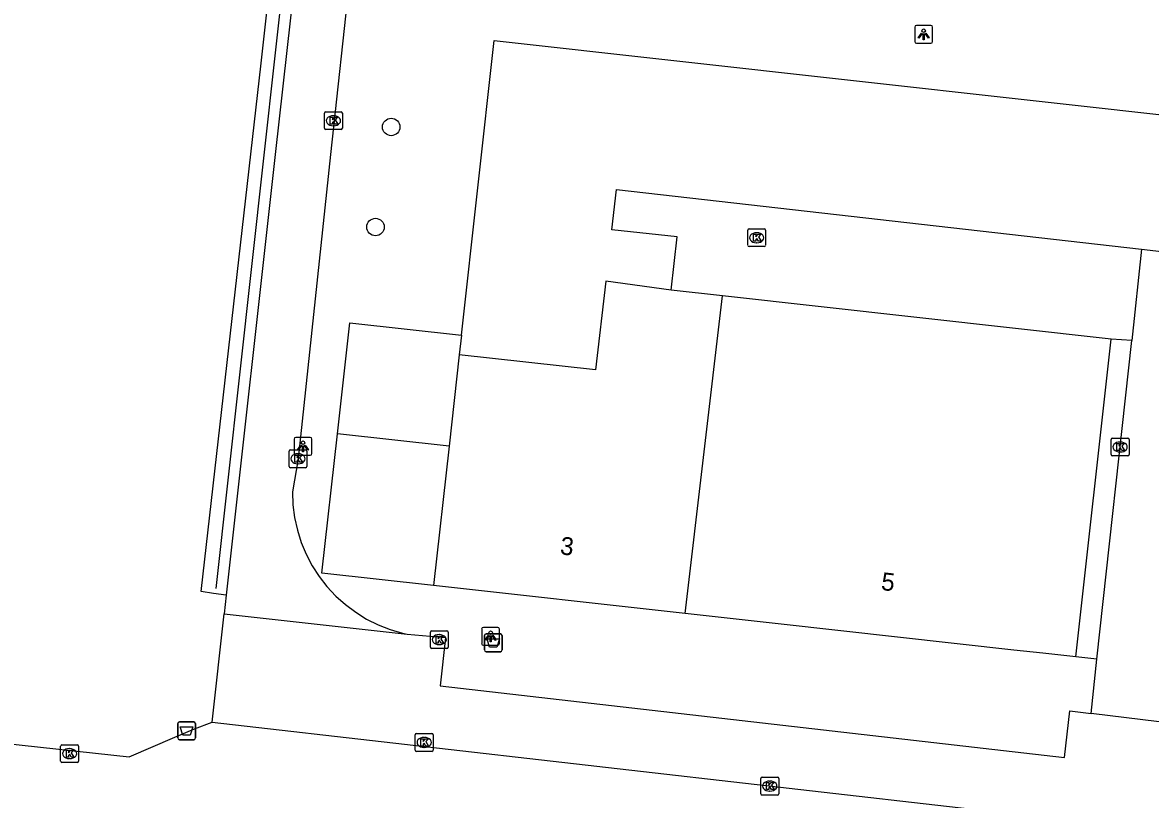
# Model space of a CAD drawing. Extents: x 162515 to 163909, y 388494 to 389773.
# Drawn here: x 162768.7 to 162831.9, y 388713.9 to 388757.4 of the extents above; entities that cross this region are included whole.
import ezdxf

# ---------------------------------------------------------------- set-up
doc = ezdxf.new("R2010")
doc.units = 0
for name, color, linetype in [('IMGEO_Afvalbak', 7, 'Continuous'), ('IMGEO_Boom', 7, 'Continuous'), ('IMGEO_Hek', 7, 'Continuous'), ('IMGEO_Kolk', 7, 'Continuous'), ('IMGEO_Lichtpunt', 7, 'Continuous'), ('IMGEO_Pand', 7, 'Continuous'), ('IMGEO_Pand_nummerreeks', 7, 'Continuous'), ('IMGEO_Voetpad_open', 7, 'Continuous')]:
    doc.layers.add(name, color=color, linetype=linetype)

msp = doc.modelspace()

# ---------------------------------------------------------------- linework, layer by layer
at = {"layer": 'IMGEO_Afvalbak'}
for p, q in [((162794.576, 388722.261), (162794.576, 388723.061)), ((162794.576, 388723.061), (162794.576, 388722.261)), ((162794.676, 388723.161), (162795.466, 388723.161)), ((162795.466, 388723.161), (162794.676, 388723.161)), ((162795.566, 388723.061), (162795.566, 388722.261)), ((162795.566, 388722.261), (162795.566, 388723.061)), ((162795.466, 388722.161), (162794.676, 388722.161)), ((162794.676, 388722.161), (162795.466, 388722.161)), ((162777.508, 388718.235), (162778.298, 388718.235)), ((162778.298, 388718.235), (162777.508, 388718.235)), ((162777.408, 388717.335), (162777.408, 388718.135)), ((162777.408, 388718.135), (162777.408, 388717.335)), ((162778.398, 388718.135), (162778.398, 388717.335)), ((162778.398, 388717.335), (162778.398, 388718.135)), ((162778.298, 388717.235), (162777.508, 388717.235)), ((162777.508, 388717.235), (162778.298, 388717.235))]:
    msp.add_line(p, q, dxfattribs=at)
for points in [[(162794.719, 388722.875), (162795.423, 388722.875), (162795.274, 388722.405), (162794.868, 388722.405), (162794.719, 388722.875)], [(162777.551, 388717.949), (162778.255, 388717.949), (162778.106, 388717.479), (162777.7, 388717.479), (162777.551, 388717.949)]]:
    msp.add_lwpolyline(points, dxfattribs=at)
for centre, start, end in [((162794.676, 388723.061), 90, 180), ((162794.676, 388723.061), 90, 180), ((162795.466, 388723.061), 0, 90), ((162795.466, 388723.061), 360, 90), ((162794.676, 388722.261), 180, 270), ((162794.676, 388722.261), 180, 270), ((162795.466, 388722.261), 270, 0), ((162795.466, 388722.261), 270, 0), ((162777.508, 388718.135), 90, 180), ((162777.508, 388718.135), 90, 180), ((162778.298, 388718.135), 0, 90), ((162778.298, 388718.135), 360, 90), ((162777.508, 388717.335), 180, 270), ((162777.508, 388717.335), 180, 270), ((162778.298, 388717.335), 270, 0), ((162778.298, 388717.335), 270, 0)]:
    msp.add_arc(centre, 0.1, start, end, dxfattribs=at)
at = {"layer": 'IMGEO_Boom'}
for centre in [(162789.357, 388751.535), (162788.475, 388745.931)]:
    msp.add_circle(centre, 0.489, dxfattribs=at)
at = {"layer": 'IMGEO_Hek'}
msp.add_lwpolyline([(162783.538, 388761.764), (162779.548, 388725.694)], dxfattribs=at)
at = {"layer": 'IMGEO_Kolk'}
for p, q in [((162785.62, 388751.459), (162785.62, 388752.311)), ((162785.695, 388752.385), (162786.547, 388752.385)), ((162786.621, 388752.311), (162786.621, 388751.459)), ((162786.108, 388752.165), (162786.133, 388752.165)), ((162786.547, 388751.385), (162785.695, 388751.385)), ((162786.131, 388751.605), (162786.106, 388751.605)), ((162809.317, 388744.908), (162809.317, 388745.76)), ((162809.392, 388745.834), (162810.244, 388745.834)), ((162809.805, 388745.614), (162809.83, 388745.614)), ((162810.318, 388745.76), (162810.318, 388744.908)), ((162810.244, 388744.834), (162809.392, 388744.834)), ((162809.828, 388745.054), (162809.803, 388745.054)), ((162829.662, 388733.193), (162829.662, 388734.045)), ((162829.737, 388734.119), (162830.589, 388734.119)), ((162830.663, 388734.045), (162830.663, 388733.193)), ((162783.639, 388732.535), (162783.639, 388733.387)), ((162783.714, 388733.461), (162784.566, 388733.461)), ((162784.64, 388733.387), (162784.64, 388732.535)), ((162830.173, 388733.339), (162830.148, 388733.339)), ((162830.15, 388733.899), (162830.175, 388733.899)), ((162784.127, 388733.241), (162784.152, 388733.241)), ((162830.589, 388733.119), (162829.737, 388733.119)), ((162784.566, 388732.461), (162783.714, 388732.461)), ((162784.15, 388732.681), (162784.125, 388732.681)), ((162791.547, 388722.409), (162791.547, 388723.261)), ((162791.622, 388723.335), (162792.474, 388723.335)), ((162792.548, 388723.261), (162792.548, 388722.409)), ((162792.035, 388723.115), (162792.06, 388723.115)), ((162792.474, 388722.335), (162791.622, 388722.335)), ((162792.058, 388722.555), (162792.033, 388722.555)), ((162790.777, 388717.58), (162791.629, 388717.58)), ((162770.927, 388716.953), (162771.779, 388716.953)), ((162790.702, 388716.654), (162790.702, 388717.506)), ((162791.19, 388717.36), (162791.215, 388717.36)), ((162791.703, 388717.506), (162791.703, 388716.654)), ((162770.852, 388716.027), (162770.852, 388716.879)), ((162771.34, 388716.733), (162771.365, 388716.733)), ((162771.853, 388716.879), (162771.853, 388716.027)), ((162791.629, 388716.58), (162790.777, 388716.58)), ((162791.213, 388716.8), (162791.188, 388716.8)), ((162771.779, 388715.953), (162770.927, 388715.953)), ((162771.363, 388716.173), (162771.338, 388716.173)), ((162810.05, 388714.211), (162810.05, 388715.063)), ((162810.125, 388715.137), (162810.977, 388715.137)), ((162811.051, 388715.063), (162811.051, 388714.211)), ((162810.538, 388714.917), (162810.563, 388714.917)), ((162810.977, 388714.137), (162810.125, 388714.137)), ((162810.561, 388714.357), (162810.536, 388714.357))]:
    msp.add_line(p, q, dxfattribs=at)
for points in [[(162785.62, 388751.459), (162785.62, 388752.311)], [(162785.695, 388752.385), (162786.547, 388752.385)], [(162786.621, 388752.311), (162786.621, 388751.459)], [(162785.941, 388752.085), (162786.064, 388752.085), (162786.064, 388751.934), (162786.194, 388752.085), (162786.358, 388752.085), (162786.212, 388751.934), (162786.365, 388751.685), (162786.213, 388751.685), (162786.128, 388751.849), (162786.064, 388751.782), (162786.064, 388751.685), (162785.941, 388751.685), (162785.941, 388752.085)], [(162786.547, 388751.385), (162785.695, 388751.385)], [(162809.317, 388744.908), (162809.317, 388745.76)], [(162809.392, 388745.834), (162810.244, 388745.834)], [(162809.638, 388745.534), (162809.761, 388745.534), (162809.761, 388745.383), (162809.891, 388745.534), (162810.055, 388745.534), (162809.909, 388745.383), (162810.062, 388745.134), (162809.91, 388745.134), (162809.825, 388745.298), (162809.761, 388745.231), (162809.761, 388745.134), (162809.638, 388745.134), (162809.638, 388745.534)], [(162810.318, 388745.76), (162810.318, 388744.908)], [(162810.244, 388744.834), (162809.392, 388744.834)], [(162829.662, 388733.193), (162829.662, 388734.045)], [(162829.737, 388734.119), (162830.589, 388734.119)], [(162830.663, 388734.045), (162830.663, 388733.193)], [(162783.639, 388732.535), (162783.639, 388733.387)], [(162783.714, 388733.461), (162784.566, 388733.461)], [(162784.64, 388733.387), (162784.64, 388732.535)], [(162829.983, 388733.819), (162830.106, 388733.819), (162830.106, 388733.668), (162830.236, 388733.819), (162830.4, 388733.819), (162830.254, 388733.668), (162830.407, 388733.419), (162830.255, 388733.419), (162830.17, 388733.583), (162830.106, 388733.516), (162830.106, 388733.419), (162829.983, 388733.419), (162829.983, 388733.819)], [(162783.96, 388733.161), (162784.083, 388733.161), (162784.083, 388733.01), (162784.213, 388733.161), (162784.377, 388733.161), (162784.231, 388733.01), (162784.384, 388732.761), (162784.232, 388732.761), (162784.147, 388732.925), (162784.083, 388732.858), (162784.083, 388732.761), (162783.96, 388732.761), (162783.96, 388733.161)], [(162830.589, 388733.119), (162829.737, 388733.119)], [(162784.566, 388732.461), (162783.714, 388732.461)], [(162791.547, 388722.409), (162791.547, 388723.261)], [(162791.622, 388723.335), (162792.474, 388723.335)], [(162792.548, 388723.261), (162792.548, 388722.409)], [(162791.868, 388723.035), (162791.991, 388723.035), (162791.991, 388722.884), (162792.121, 388723.035), (162792.285, 388723.035), (162792.139, 388722.884), (162792.292, 388722.635), (162792.14, 388722.635), (162792.055, 388722.799), (162791.991, 388722.732), (162791.991, 388722.635), (162791.868, 388722.635), (162791.868, 388723.035)], [(162792.474, 388722.335), (162791.622, 388722.335)], [(162790.777, 388717.58), (162791.629, 388717.58)], [(162770.927, 388716.953), (162771.779, 388716.953)], [(162790.702, 388716.654), (162790.702, 388717.506)], [(162791.023, 388717.28), (162791.146, 388717.28), (162791.146, 388717.129), (162791.276, 388717.28), (162791.44, 388717.28), (162791.294, 388717.129), (162791.447, 388716.88), (162791.295, 388716.88), (162791.21, 388717.044), (162791.146, 388716.977), (162791.146, 388716.88), (162791.023, 388716.88), (162791.023, 388717.28)], [(162791.703, 388717.506), (162791.703, 388716.654)], [(162770.852, 388716.027), (162770.852, 388716.879)], [(162771.173, 388716.653), (162771.296, 388716.653), (162771.296, 388716.502), (162771.426, 388716.653), (162771.59, 388716.653), (162771.444, 388716.502), (162771.597, 388716.253), (162771.445, 388716.253), (162771.36, 388716.417), (162771.296, 388716.35), (162771.296, 388716.253), (162771.173, 388716.253), (162771.173, 388716.653)], [(162771.853, 388716.879), (162771.853, 388716.027)], [(162791.629, 388716.58), (162790.777, 388716.58)], [(162771.779, 388715.953), (162770.927, 388715.953)], [(162810.05, 388714.211), (162810.05, 388715.063)], [(162810.125, 388715.137), (162810.977, 388715.137)], [(162811.051, 388715.063), (162811.051, 388714.211)], [(162810.371, 388714.837), (162810.494, 388714.837), (162810.494, 388714.686), (162810.624, 388714.837), (162810.788, 388714.837), (162810.642, 388714.686), (162810.795, 388714.437), (162810.643, 388714.437), (162810.558, 388714.601), (162810.494, 388714.534), (162810.494, 388714.437), (162810.371, 388714.437), (162810.371, 388714.837)], [(162810.977, 388714.137), (162810.125, 388714.137)]]:
    msp.add_lwpolyline(points, dxfattribs=at)
for centre, start, end in [((162785.697, 388752.309), 91.55205, 178.44795), ((162785.697, 388752.309), 91.55205, 178.44795), ((162786.545, 388752.309), 1.55205, 88.44795), ((162786.545, 388752.309), 1.55205, 88.44795), ((162785.697, 388751.461), 181.55205, 268.44795), ((162785.697, 388751.461), 181.55205, 268.44795), ((162786.545, 388751.461), 271.55205, 358.44795), ((162786.545, 388751.461), 271.55205, 358.44795), ((162809.394, 388745.758), 91.55205, 178.44795), ((162809.394, 388745.758), 91.55205, 178.44795), ((162810.242, 388745.758), 1.55205, 88.44795), ((162810.242, 388745.758), 1.55205, 88.44795), ((162809.394, 388744.91), 181.55205, 268.44795), ((162809.394, 388744.91), 181.55205, 268.44795), ((162810.242, 388744.91), 271.55205, 358.44795), ((162810.242, 388744.91), 271.55205, 358.44795), ((162829.739, 388734.043), 91.55205, 178.44795), ((162829.739, 388734.043), 91.55205, 178.44795), ((162830.587, 388734.043), 1.55205, 88.44795), ((162830.587, 388734.043), 1.55205, 88.44795), ((162783.716, 388733.385), 91.55205, 178.44795), ((162783.716, 388733.385), 91.55205, 178.44795), ((162784.564, 388733.385), 1.55205, 88.44795), ((162784.564, 388733.385), 1.55205, 88.44795), ((162829.739, 388733.195), 181.55205, 268.44795), ((162829.739, 388733.195), 181.55205, 268.44795), ((162830.587, 388733.195), 271.55205, 358.44795), ((162830.587, 388733.195), 271.55205, 358.44795), ((162783.716, 388732.537), 181.55205, 268.44795), ((162783.716, 388732.537), 181.55205, 268.44795), ((162784.564, 388732.537), 271.55205, 358.44795), ((162784.564, 388732.537), 271.55205, 358.44795), ((162791.624, 388723.259), 91.55205, 178.44795), ((162791.624, 388723.259), 91.55205, 178.44795), ((162792.472, 388723.259), 1.55205, 88.44795), ((162792.472, 388723.259), 1.55205, 88.44795), ((162791.624, 388722.411), 181.55205, 268.44795), ((162791.624, 388722.411), 181.55205, 268.44795), ((162792.472, 388722.411), 271.55205, 358.44795), ((162792.472, 388722.411), 271.55205, 358.44795), ((162790.779, 388717.504), 91.55205, 178.44795), ((162790.779, 388717.504), 91.55205, 178.44795), ((162791.627, 388717.504), 1.55205, 88.44795), ((162791.627, 388717.504), 1.55205, 88.44795), ((162770.929, 388716.877), 91.55205, 178.44795), ((162770.929, 388716.877), 91.55205, 178.44795), ((162771.777, 388716.877), 1.55205, 88.44795), ((162771.777, 388716.877), 1.55205, 88.44795), ((162790.779, 388716.656), 181.55205, 268.44795), ((162790.779, 388716.656), 181.55205, 268.44795), ((162791.627, 388716.656), 271.55205, 358.44795), ((162791.627, 388716.656), 271.55205, 358.44795), ((162770.929, 388716.029), 181.55205, 268.44795), ((162770.929, 388716.029), 181.55205, 268.44795), ((162771.777, 388716.029), 271.55205, 358.44795), ((162771.777, 388716.029), 271.55205, 358.44795), ((162810.127, 388715.061), 91.55205, 178.44795), ((162810.127, 388715.061), 91.55205, 178.44795), ((162810.975, 388715.061), 1.55205, 88.44795), ((162810.975, 388715.061), 1.55205, 88.44795), ((162810.127, 388714.213), 181.55205, 268.44795), ((162810.127, 388714.213), 181.55205, 268.44795), ((162810.975, 388714.213), 271.55205, 358.44795), ((162810.975, 388714.213), 271.55205, 358.44795)]:
    msp.add_arc(centre, 0.0765, start, end, dxfattribs=at)
for centre, major_axis, ratio, start_param, end_param in [((162786.107, 388751.885), (-0.387, 0.002), 0.722429, 4.712389, 7.853982), ((162786.132, 388751.885), (-0.39, 0.002), 0.717154, 1.570796, 4.712389), ((162809.804, 388745.334), (-0.387, 0.002), 0.722429, 4.712389, 7.853982), ((162809.829, 388745.334), (-0.39, 0.002), 0.717154, 1.570796, 4.712389), ((162830.149, 388733.619), (-0.387, 0.002), 0.722429, 4.712389, 7.853982), ((162830.174, 388733.619), (-0.39, 0.002), 0.717154, 1.570796, 4.712389), ((162784.126, 388732.961), (-0.387, 0.002), 0.722429, 4.712389, 7.853982), ((162784.151, 388732.961), (-0.39, 0.002), 0.717154, 1.570796, 4.712389), ((162792.034, 388722.835), (-0.387, 0.002), 0.722429, 4.712389, 7.853982), ((162792.059, 388722.835), (-0.39, 0.002), 0.717154, 1.570796, 4.712389), ((162791.189, 388717.08), (-0.387, 0.002), 0.722429, 4.712389, 7.853982), ((162791.214, 388717.08), (-0.39, 0.002), 0.717154, 1.570796, 4.712389), ((162771.339, 388716.453), (-0.387, 0.002), 0.722429, 4.712389, 7.853982), ((162771.364, 388716.453), (-0.39, 0.002), 0.717154, 1.570796, 4.712389), ((162810.537, 388714.637), (-0.387, 0.002), 0.722429, 4.712389, 7.853982), ((162810.562, 388714.637), (-0.39, 0.002), 0.717154, 1.570796, 4.712389)]:
    msp.add_ellipse(centre, major_axis=major_axis, ratio=ratio, start_param=start_param, end_param=end_param, dxfattribs=at)
at = {"layer": 'IMGEO_Lichtpunt'}
for p, q in [((162818.668, 388757.124), (162818.668, 388756.317)), ((162818.668, 388757.124), (162818.668, 388756.317)), ((162819.57, 388757.219), (162818.762, 388757.219)), ((162819.57, 388757.219), (162818.762, 388757.219)), ((162819.664, 388756.317), (162819.664, 388757.124)), ((162819.664, 388756.317), (162819.664, 388757.124)), ((162818.762, 388756.223), (162819.57, 388756.223)), ((162818.762, 388756.223), (162819.57, 388756.223)), ((162783.919, 388734.062), (162783.919, 388733.255)), ((162783.919, 388734.062), (162783.919, 388733.255)), ((162784.821, 388734.157), (162784.013, 388734.157)), ((162784.821, 388734.157), (162784.013, 388734.157)), ((162784.915, 388733.255), (162784.915, 388734.062)), ((162784.915, 388733.255), (162784.915, 388734.062)), ((162784.013, 388733.161), (162784.821, 388733.161)), ((162784.013, 388733.161), (162784.821, 388733.161)), ((162794.421, 388723.423), (162794.421, 388722.616)), ((162794.421, 388723.423), (162794.421, 388722.616)), ((162795.323, 388723.518), (162794.515, 388723.518)), ((162795.323, 388723.518), (162794.515, 388723.518)), ((162795.417, 388722.616), (162795.417, 388723.423)), ((162795.417, 388722.616), (162795.417, 388723.423)), ((162794.515, 388722.522), (162795.323, 388722.522)), ((162794.515, 388722.522), (162795.323, 388722.522))]:
    msp.add_line(p, q, dxfattribs=at)
for points in [[(162819.042, 388756.788), (162819.081, 388756.76), (162818.893, 388756.498), (162818.855, 388756.525), (162819.042, 388756.788)], [(162819.144, 388756.74), (162819.191, 388756.74), (162819.191, 388756.418), (162819.144, 388756.418), (162819.144, 388756.74)], [(162819.254, 388756.76), (162819.292, 388756.787), (162819.479, 388756.525), (162819.44, 388756.497), (162819.254, 388756.76)], [(162784.293, 388733.726), (162784.332, 388733.698), (162784.144, 388733.436), (162784.106, 388733.463), (162784.293, 388733.726)], [(162784.395, 388733.678), (162784.442, 388733.678), (162784.442, 388733.356), (162784.395, 388733.356), (162784.395, 388733.678)], [(162784.505, 388733.698), (162784.543, 388733.725), (162784.73, 388733.463), (162784.691, 388733.435), (162784.505, 388733.698)], [(162794.795, 388723.087), (162794.834, 388723.059), (162794.646, 388722.797), (162794.608, 388722.824), (162794.795, 388723.087)], [(162794.897, 388723.039), (162794.944, 388723.039), (162794.944, 388722.717), (162794.897, 388722.717), (162794.897, 388723.039)], [(162795.007, 388723.059), (162795.045, 388723.086), (162795.232, 388722.824), (162795.193, 388722.796), (162795.007, 388723.059)]]:
    msp.add_lwpolyline(points, dxfattribs=at)
for centre in [(162819.167, 388756.922), (162784.418, 388733.86), (162794.92, 388723.221)]:
    msp.add_circle(centre, 0.0994, dxfattribs=at)
for centre, start, end in [((162818.762, 388757.124), 90, 180), ((162818.762, 388757.124), 90, 180), ((162819.57, 388757.124), 0, 90), ((162819.57, 388757.124), 0, 90), ((162818.762, 388756.317), 180, 270), ((162818.762, 388756.317), 180, 270), ((162819.57, 388756.317), 270, 0), ((162819.57, 388756.317), 270, 360), ((162784.013, 388734.062), 90, 180), ((162784.013, 388734.062), 90, 180), ((162784.821, 388734.062), 0, 90), ((162784.821, 388734.062), 0, 90), ((162784.013, 388733.255), 180, 270), ((162784.013, 388733.255), 180, 270), ((162784.821, 388733.255), 270, 0), ((162784.821, 388733.255), 270, 360), ((162794.515, 388723.423), 90, 180), ((162794.515, 388723.423), 90, 180), ((162795.323, 388723.423), 0, 90), ((162795.323, 388723.423), 0, 90), ((162794.515, 388722.616), 180, 270), ((162794.515, 388722.616), 180, 270), ((162795.323, 388722.616), 270, 0), ((162795.323, 388722.616), 270, 360)]:
    msp.add_arc(centre, 0.0946, start, end, dxfattribs=at)
at = {"layer": 'IMGEO_Pand'}
for points in [[(162793.287, 388739.876), (162795.118, 388756.373), (162845.081, 388750.819), (162842.265, 388727.462)], [(162805.036, 388742.393), (162805.366, 388745.376), (162801.707, 388745.78), (162801.971, 388748.041), (162831.367, 388744.685)], [(162831.367, 388744.685), (162835.187, 388744.249)], [(162805.036, 388742.393), (162801.37, 388742.896), (162800.79, 388737.93), (162793.165, 388738.779)], [(162807.897, 388742.075), (162805.036, 388742.393)], [(162805.821, 388724.296), (162807.897, 388742.075)], [(162829.651, 388739.658), (162807.897, 388742.075)], [(162793.287, 388739.876), (162793.165, 388738.779)], [(162827.673, 388721.867), (162829.651, 388739.658)], [(162793.165, 388738.779), (162792.596, 388733.657)], [(162792.596, 388733.657), (162791.731, 388725.862)], [(162805.821, 388724.296), (162791.731, 388725.862)], [(162827.673, 388721.867), (162825.835, 388722.071), (162824.203, 388722.252), (162811.184, 388723.7), (162805.821, 388724.296)]]:
    msp.add_lwpolyline(points, dxfattribs=at)
at = {"layer": 'IMGEO_Voetpad_open'}
for points in [[(162780.12, 388725.328), (162779.405, 388725.427), (162778.724, 388725.521), (162782.069, 388755.112), (162782.886, 388762.34), (162784.221, 388762.216)], [(162784.221, 388762.216), (162784.139, 388761.491), (162782.862, 388750), (162780.12, 388725.328)], [(162787.054, 388760.164), (162785.965, 388750), (162784.14, 388732.957), (162783.832, 388731.104), (162783.858, 388730.384), (162783.948, 388729.669), (162784.102, 388728.965), (162784.317, 388728.278), (162784.594, 388727.613), (162784.929, 388726.975), (162785.319, 388726.369), (162785.762, 388725.801), (162786.254, 388725.275), (162786.791, 388724.794), (162787.368, 388724.364), (162787.982, 388723.987), (162788.627, 388723.666), (162789.299, 388723.404), (162789.99, 388723.203), (162790.244, 388723.146)], [(162831.367, 388744.685), (162830.811, 388739.588)], [(162786.346, 388734.36), (162787.046, 388740.569), (162793.287, 388739.876)], [(162830.811, 388739.588), (162829.651, 388739.658)], [(162828.866, 388721.737), (162830.811, 388739.588)], [(162791.731, 388725.862), (162785.467, 388726.559), (162786.346, 388734.36)], [(162792.596, 388733.657), (162786.346, 388734.36)], [(162780.12, 388725.328), (162780.004, 388724.284)], [(162779.329, 388718.213), (162780.004, 388724.284)], [(162780.004, 388724.284), (162790.244, 388723.146)], [(162705.509, 388719.489), (162706.051, 388723.761), (162774.678, 388716.282), (162777.249, 388717.372), (162778.349, 388717.838), (162779.329, 388718.213)], [(162790.244, 388723.146), (162792.398, 388722.946), (162792.106, 388720.253), (162827.047, 388716.24), (162827.338, 388718.851), (162828.535, 388718.703)], [(162828.866, 388721.737), (162827.673, 388721.867)], [(162828.535, 388718.703), (162828.866, 388721.737)], [(162779.329, 388718.213), (162822.4, 388713.295), (162822.606, 388713.269), (162823.334, 388713.136), (162824.046, 388712.938), (162824.738, 388712.678), (162825.405, 388712.357), (162826.039, 388711.977), (162826.638, 388711.542), (162827.195, 388711.056), (162827.706, 388710.522), (162828.168, 388709.944), (162828.576, 388709.327), (162828.927, 388708.676), (162829.219, 388707.997), (162829.449, 388707.294)], [(162832.351, 388718.232), (162828.535, 388718.703)]]:
    msp.add_lwpolyline(points, dxfattribs=at)

# ---------------------------------------------------------------- texts
at = {"layer": 'IMGEO_Pand_nummerreeks'}
for s, rotation, p in [('3', 353.65802, (162798.78, 388727.614)), ('5', 353.65722, (162816.751, 388725.617))]:
    msp.add_text(s, height=1, rotation=rotation, dxfattribs=at).set_placement(p)

doc.saveas('drawing.dxf')
